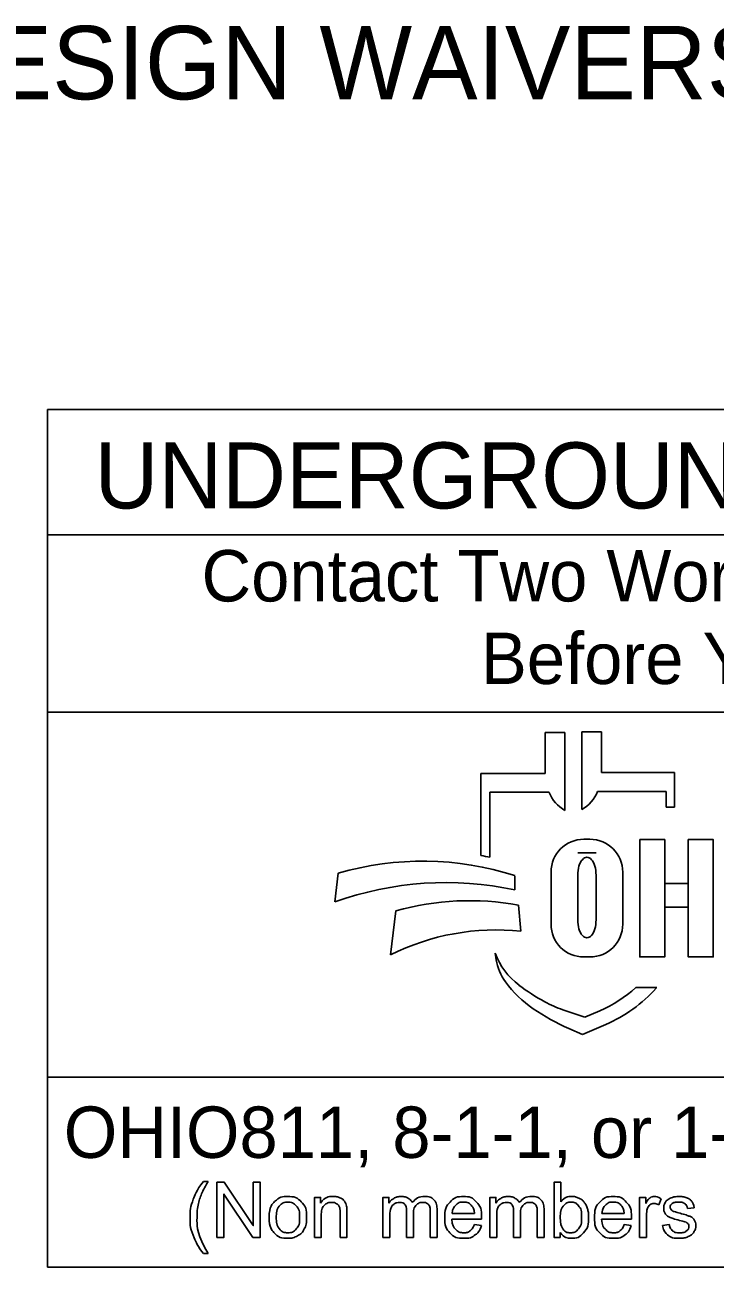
# Model space of a CAD drawing. Extents: x 0 to 34, y 0 to 22.
# Drawn here: x 2.743 to 4.623, y 2.143 to 5.529 of the extents above; entities that cross this region are included whole.
import ezdxf

# ---------------------------------------------------------------- set-up
doc = ezdxf.new("R2010")
doc.units = 0
doc.layers.add('SH_Data', color=7, linetype='Continuous')
doc.layers.add('SH_Text', color=7, linetype='Continuous')

msp = doc.modelspace()

# ---------------------------------------------------------------- linework, layer by layer
at = {"layer": 'SH_Data'}
for p, q in [((2.8045, 2.1428), (2.8045, 4.4803)), ((7.0545, 4.4803), (2.8045, 4.4803)), ((2.8045, 4.1387), (7.0545, 4.1387)), ((2.8045, 3.6553), (7.0545, 3.6553)), ((7.0545, 2.6607), (2.8045, 2.6607)), ((7.0545, 2.1428), (2.8045, 2.1428))]:
    msp.add_line(p, q, dxfattribs=at)
at = {"layer": 'SH_Text'}
for p, q in [((4.1606, 3.4883), (4.1606, 3.5998)), ((4.1606, 3.5998), (4.2142, 3.5998)), ((4.2142, 3.5998), (4.2142, 3.3877)), ((4.2599, 3.39), (4.2599, 3.6021)), ((4.2599, 3.6021), (4.3135, 3.6021)), ((4.3135, 3.6021), (4.3135, 3.4906)), ((3.9846, 3.2644), (3.9846, 3.4883)), ((3.9846, 3.4883), (4.1606, 3.4883)), ((4.3135, 3.4906), (4.5128, 3.4906)), ((4.5128, 3.4906), (4.5128, 3.3968)), ((4.0098, 3.4369), (4.0098, 3.26)), ((4.171, 3.4369), (4.0098, 3.4369)), ((4.4895, 3.4392), (4.3031, 3.4392)), ((4.4895, 3.3968), (4.4895, 3.4392)), ((4.5128, 3.3968), (4.4895, 3.3968)), ((4.2656, 3.3091), (4.2821, 3.3091)), ((4.2988, 3.2721), (4.249, 3.2721)), ((4.1761, 3.0776), (4.1761, 3.2196)), ((4.3716, 3.2196), (4.3716, 3.0776)), ((3.5872, 3.1381), (3.5966, 3.2162)), ((4.0779, 3.2097), (4.0779, 3.1709)), ((4.249, 3.089), (4.249, 3.2114)), ((4.2988, 3.2114), (4.2988, 3.089)), ((4.0879, 3.1291), (4.0941, 3.0582)), ((3.7391, 2.9936), (3.7537, 3.1137)), ((4.0268, 2.9807), (4.0237, 2.9986)), ((4.2821, 2.9882), (4.2656, 2.9882)), ((4.407, 2.9048), (4.4645, 2.9048)), ((4.2086, 2.8444), (4.268, 2.8239)), ((4.268, 2.8239), (4.3091, 2.8417)), ((4.262, 2.7769), (4.2247, 2.7934)), ((4.3253, 2.8044), (4.262, 2.7769))]:
    msp.add_line(p, q, dxfattribs=at)
for points in [[(4.418, 3.3081), (4.4859, 3.3081), (4.4859, 2.9881), (4.418, 2.9881)], [(4.5501, 3.3081), (4.6181, 3.3081), (4.6181, 2.9881), (4.5501, 2.9881)], [(4.4859, 3.1882), (4.5501, 3.1882), (4.5501, 3.1242), (4.4859, 3.1242)]]:
    msp.add_lwpolyline(points, close=True, dxfattribs=at)
for points in [[(3.2291, 2.3766), (3.2423, 2.3766)], [(3.2659, 2.2239), (3.2659, 2.3741), (3.2862, 2.3741), (3.3652, 2.2561), (3.3652, 2.3741), (3.3842, 2.3741), (3.3842, 2.2239), (3.3639, 2.2239), (3.2849, 2.3419), (3.2849, 2.2239), (3.2659, 2.2239)], [(4.2013, 2.2239), (4.1843, 2.2239), (4.1843, 2.3741), (4.2027, 2.3741), (4.2027, 2.3206)], [(3.5319, 2.2239), (3.5319, 2.3328), (3.5484, 2.3328), (3.5484, 2.3173)], [(3.7183, 2.2239), (3.7183, 2.3328), (3.7347, 2.3328), (3.7347, 2.3174)], [(4.0096, 2.2239), (4.0096, 2.3328), (4.0261, 2.3328), (4.0261, 2.3174)], [(4.4174, 2.2239), (4.4174, 2.3328), (4.434, 2.3328), (4.434, 2.3163)], [(4.4765, 2.3293), (4.47, 2.3122)], [(4.5664, 2.3046), (4.5483, 2.3022)], [(3.5503, 2.2833), (3.5503, 2.2239), (3.5319, 2.2239)], [(3.6202, 2.2908), (3.6202, 2.2239), (3.6018, 2.2239), (3.6018, 2.2901)], [(3.7367, 2.2803), (3.7367, 2.2239), (3.7183, 2.2239)], [(3.8013, 2.2871), (3.8013, 2.2239), (3.7829, 2.2239), (3.7829, 2.2946)], [(3.8658, 2.2986), (3.8658, 2.2239), (3.8474, 2.2239), (3.8474, 2.2924)], [(3.987, 2.2736), (3.9059, 2.2736)], [(3.9069, 2.2887), (3.9677, 2.2887)], [(4.0281, 2.2803), (4.0281, 2.2239), (4.0096, 2.2239)], [(4.0927, 2.2871), (4.0927, 2.2239), (4.0743, 2.2239), (4.0743, 2.2946)], [(4.1572, 2.2986), (4.1572, 2.2239), (4.1387, 2.2239), (4.1387, 2.2924)], [(4.395, 2.2736), (4.3138, 2.2736)], [(4.3149, 2.2887), (4.3756, 2.2887)], [(4.4358, 2.2809), (4.4358, 2.2239), (4.4174, 2.2239)], [(3.9674, 2.2591), (3.9865, 2.2567)], [(4.2013, 2.2375), (4.2013, 2.2239)], [(4.3754, 2.2591), (4.3945, 2.2567)], [(4.48, 2.2564), (4.4982, 2.2593)], [(3.2423, 2.1798), (3.2291, 2.1798)]]:
    msp.add_lwpolyline(points, dxfattribs=at)
for centre, radius, start, end in [((4.2623, 3.4736), 0.0985, 201.9296, 240.7469), ((4.2118, 3.476), 0.0985, 299.2531, 338.0704), ((4.2656, 3.2196), 0.0895, 90, 180), ((4.2821, 3.2196), 0.0895, 0, 90), ((3.8565, 2.4554), 0.8191, 79.2074, 81.0007), ((3.8267, 2.4302), 0.8191, 72.1402, 106.3144), ((3.8898, 2.2991), 0.8919, 77.8238, 109.8274), ((3.9537, 2.4094), 0.7322, 79.44, 105.8467), ((4.0257, 2.4262), 0.6357, 83.8248, 116.8021), ((4.2656, 3.0776), 0.0895, 180, 270), ((4.2821, 3.0776), 0.0895, 270, 0), ((4.2111, 3.0707), 0.2008, 201.0457, 232.5314), ((4.1681, 3.0048), 0.1433, 189.6817, 216.0884), ((4.3017, 3.1022), 0.3088, 216.0884, 235.7167), ((4.4036, 3.3219), 0.5173, 232.5314, 241.794), ((4.1657, 3.1722), 0.3602, 293.4582, 312.0712), ((4.1657, 3.1722), 0.401, 293.4582, 317.8286), ((4.4682, 3.3465), 0.6044, 235.7167, 246.2325), ((4.3185, 3.1631), 0.3371, 241.794, 250.9821)]:
    msp.add_arc(centre, radius, start, end, dxfattribs=at)
for centre, start_param, end_param in [((4.2739, 3.2114), 4.712389, 7.853982), ((4.2739, 3.089), 1.570796, 4.712389)]:
    msp.add_ellipse(centre, major_axis=(0, 0.0484), ratio=0.514403, start_param=start_param, end_param=end_param, dxfattribs=at)
for points in [[(3.2291, 2.1798), (3.2139, 2.199), (3.2033, 2.2248), (3.1928, 2.2506), (3.1928, 2.2783), (3.1928, 2.3026), (3.2006, 2.325), (3.2099, 2.3509), (3.2291, 2.3766)], [(3.2423, 2.3766), (3.2299, 2.3553), (3.226, 2.3462), (3.2197, 2.332), (3.2161, 2.3167), (3.2118, 2.2975), (3.2118, 2.2782), (3.2118, 2.2289), (3.2423, 2.1798)], [(3.4084, 2.2783), (3.4084, 2.3085), (3.4252, 2.3231), (3.4392, 2.3352), (3.4593, 2.3352), (3.4818, 2.3352), (3.496, 2.3205), (3.5102, 2.3058), (3.5102, 2.2799), (3.5102, 2.2589), (3.5039, 2.2469), (3.4976, 2.2348), (3.4856, 2.2282), (3.4736, 2.2215), (3.4593, 2.2215), (3.4365, 2.2215), (3.4224, 2.2362), (3.4084, 2.2508), (3.4084, 2.2783)], [(3.4274, 2.2783), (3.4274, 2.2574), (3.4365, 2.247), (3.4456, 2.2366), (3.4593, 2.2366), (3.473, 2.2366), (3.4821, 2.2471), (3.4912, 2.2575), (3.4912, 2.279), (3.4912, 2.2991), (3.4821, 2.3095), (3.4729, 2.3199), (3.4593, 2.3199), (3.4456, 2.3199), (3.4365, 2.3096), (3.4274, 2.2992), (3.4274, 2.2783)], [(3.5484, 2.3173), (3.5604, 2.3352), (3.583, 2.3352), (3.5929, 2.3352), (3.6011, 2.3316), (3.6094, 2.3281), (3.6134, 2.3224), (3.6175, 2.3166), (3.6192, 2.3087), (3.6202, 2.3036), (3.6202, 2.2908)], [(3.6018, 2.2901), (3.6018, 2.3013), (3.5996, 2.3069), (3.5975, 2.3125), (3.592, 2.3158), (3.5865, 2.3191), (3.5791, 2.3191), (3.5674, 2.3191), (3.5588, 2.3117), (3.5503, 2.3042), (3.5503, 2.2833)], [(3.7347, 2.3174), (3.7399, 2.3254), (3.7484, 2.3303), (3.7569, 2.3352), (3.7677, 2.3352), (3.7798, 2.3352), (3.7876, 2.3301), (3.7953, 2.3251), (3.7985, 2.3161), (3.8114, 2.3352), (3.8321, 2.3352), (3.8483, 2.3352), (3.8571, 2.3262), (3.8658, 2.3172), (3.8658, 2.2986)], [(3.7829, 2.2946), (3.7829, 2.3069), (3.7784, 2.313), (3.7739, 2.3191), (3.7636, 2.3191), (3.7559, 2.3191), (3.7492, 2.315), (3.7426, 2.311), (3.7397, 2.3031), (3.7367, 2.2952), (3.7367, 2.2803)], [(3.8474, 2.2924), (3.8474, 2.3035), (3.8456, 2.3083), (3.8438, 2.3132), (3.8391, 2.3162), (3.8343, 2.3191), (3.828, 2.3191), (3.8165, 2.3191), (3.8089, 2.3115), (3.8013, 2.3039), (3.8013, 2.2871)], [(3.9865, 2.2567), (3.982, 2.24), (3.9698, 2.2307), (3.9576, 2.2215), (3.9387, 2.2215), (3.9148, 2.2215), (3.9008, 2.2362), (3.8869, 2.2509), (3.8869, 2.2774), (3.8869, 2.3049), (3.901, 2.32), (3.9151, 2.3352), (3.9376, 2.3352), (3.9595, 2.3352), (3.9733, 2.3203), (3.9871, 2.3055), (3.9871, 2.2785), (3.9871, 2.2769), (3.987, 2.2736)], [(3.9677, 2.2887), (3.9664, 2.3025), (3.9607, 2.3094), (3.9519, 2.3201), (3.9378, 2.3201), (3.9251, 2.3201), (3.9165, 2.3115), (3.9078, 2.303), (3.9069, 2.2887)], [(4.0261, 2.3174), (4.0312, 2.3254), (4.0397, 2.3303), (4.0482, 2.3352), (4.0591, 2.3352), (4.0712, 2.3352), (4.0789, 2.3301), (4.0867, 2.3251), (4.0899, 2.3161), (4.1028, 2.3352), (4.1235, 2.3352), (4.1397, 2.3352), (4.1484, 2.3262), (4.1572, 2.3172), (4.1572, 2.2986)], [(4.0743, 2.2946), (4.0743, 2.3069), (4.0698, 2.313), (4.0653, 2.3191), (4.055, 2.3191), (4.0472, 2.3191), (4.0406, 2.315), (4.034, 2.311), (4.031, 2.3031), (4.0281, 2.2952), (4.0281, 2.2803)], [(4.1387, 2.2924), (4.1387, 2.3035), (4.1369, 2.3083), (4.1351, 2.3132), (4.1304, 2.3162), (4.1257, 2.3191), (4.1194, 2.3191), (4.1079, 2.3191), (4.1003, 2.3115), (4.0927, 2.3039), (4.0927, 2.2871)], [(4.2011, 2.2792), (4.2011, 2.2596), (4.2064, 2.2509), (4.2151, 2.2366), (4.2299, 2.2366), (4.242, 2.2366), (4.2508, 2.2471), (4.2596, 2.2576), (4.2596, 2.2784), (4.2596, 2.2998), (4.2512, 2.3099), (4.2427, 2.3201), (4.2308, 2.3201), (4.2187, 2.3201), (4.2099, 2.3096), (4.2011, 2.299), (4.2011, 2.2792)], [(4.2027, 2.3206), (4.2144, 2.3352), (4.2325, 2.3352), (4.2426, 2.3352), (4.2515, 2.3311), (4.2605, 2.3271), (4.2663, 2.3198), (4.272, 2.3124), (4.2753, 2.3021), (4.2786, 2.2918), (4.2786, 2.28), (4.2786, 2.252), (4.2648, 2.2368), (4.2509, 2.2215), (4.2316, 2.2215), (4.2123, 2.2215), (4.2013, 2.2375)], [(4.3945, 2.2567), (4.39, 2.24), (4.3778, 2.2307), (4.3656, 2.2215), (4.3467, 2.2215), (4.3228, 2.2215), (4.3088, 2.2362), (4.2948, 2.2509), (4.2948, 2.2774), (4.2948, 2.3049), (4.309, 2.32), (4.3231, 2.3352), (4.3456, 2.3352), (4.3674, 2.3352), (4.3813, 2.3203), (4.3951, 2.3055), (4.3951, 2.2785), (4.3951, 2.2769), (4.395, 2.2736)], [(4.3756, 2.2887), (4.3744, 2.3025), (4.3687, 2.3094), (4.3599, 2.3201), (4.3458, 2.3201), (4.3331, 2.3201), (4.3245, 2.3115), (4.3158, 2.303), (4.3149, 2.2887)], [(4.434, 2.3163), (4.4404, 2.3278), (4.4457, 2.3315), (4.4511, 2.3352), (4.4575, 2.3352), (4.4669, 2.3352), (4.4765, 2.3293)], [(4.47, 2.3122), (4.4633, 2.3162), (4.4566, 2.3162), (4.4505, 2.3162), (4.4457, 2.3125), (4.441, 2.3089), (4.4389, 2.3024), (4.4358, 2.2926), (4.4358, 2.2809)], [(4.5483, 2.3022), (4.5471, 2.3106), (4.5412, 2.3153), (4.5353, 2.3201), (4.5245, 2.3201), (4.5118, 2.3201), (4.5064, 2.3159), (4.501, 2.3116), (4.501, 2.306), (4.501, 2.3024), (4.5032, 2.2995), (4.5055, 2.2966), (4.5103, 2.2946), (4.5131, 2.2936), (4.5266, 2.2899), (4.5462, 2.2847), (4.5539, 2.2813), (4.5617, 2.278), (4.5661, 2.2717), (4.5705, 2.2653), (4.5705, 2.2559), (4.5705, 2.2467), (4.5652, 2.2386), (4.5598, 2.2304), (4.5496, 2.226), (4.5394, 2.2215), (4.5266, 2.2215), (4.5054, 2.2215), (4.4942, 2.2303), (4.4831, 2.2391), (4.48, 2.2564)], [(4.4982, 2.2593), (4.4998, 2.2483), (4.5068, 2.2425), (4.5138, 2.2366), (4.5265, 2.2366), (4.5392, 2.2366), (4.5454, 2.2418), (4.5515, 2.247), (4.5515, 2.254), (4.5515, 2.2602), (4.5461, 2.2638), (4.5423, 2.2663), (4.5272, 2.2701), (4.5069, 2.2752), (4.4991, 2.2789), (4.4912, 2.2827), (4.4872, 2.2893), (4.4831, 2.2959), (4.4831, 2.3038), (4.4831, 2.3111), (4.4864, 2.3173), (4.4898, 2.3235), (4.4955, 2.3276), (4.4998, 2.3308), (4.5073, 2.333), (4.5147, 2.3352), (4.5232, 2.3352), (4.5361, 2.3352), (4.5457, 2.3315), (4.5554, 2.3278), (4.5601, 2.3215), (4.5647, 2.3152), (4.5664, 2.3046)], [(3.9059, 2.2736), (3.9069, 2.2557), (3.916, 2.2462), (3.9251, 2.2366), (3.9387, 2.2366), (3.9489, 2.2366), (3.9561, 2.242), (3.9632, 2.2473), (3.9674, 2.2591)], [(4.3138, 2.2736), (4.3149, 2.2557), (4.324, 2.2462), (4.3331, 2.2366), (4.3467, 2.2366), (4.3569, 2.2366), (4.3641, 2.242), (4.3712, 2.2473), (4.3754, 2.2591)]]:
    msp.add_open_spline(points, degree=3, dxfattribs=at)

# ---------------------------------------------------------------- texts
for s, height, p in [('ADA DESIGN WAIVERS', 0.2, (1.8214, 5.3256)), ('UNDERGROUND UTILITIES', 0.18, (2.9327, 4.2106)), ('Contact Two Working Days', 0.14, (3.2242, 3.9571)), ('Before You Dig', 0.14, (3.9854, 3.7321)), ('OHIO811, 8-1-1, or 1-800-362-2764', 0.14, (2.849, 2.4406))]:
    msp.add_text(s, height=height, dxfattribs=at).set_placement(p)

doc.saveas('drawing.dxf')
